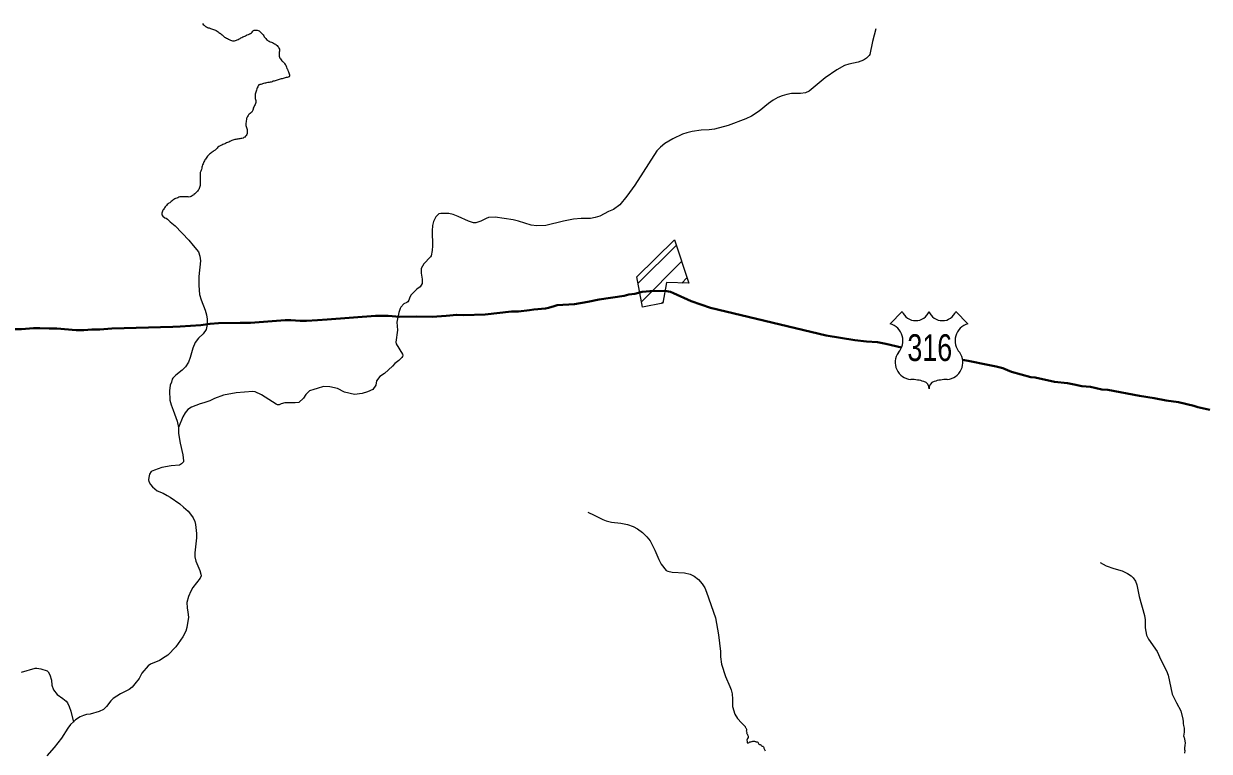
# Model space of a CAD drawing. Extents: x 553962 to 842807, y 8883888 to 9032388.
# Drawn here: x 610929 to 614032, y 8911161 to 8913066 of the extents above; entities that cross this region are included whole.
import ezdxf
from ezdxf.enums import TextEntityAlignment as Align

# ---------------------------------------------------------------- set-up
doc = ezdxf.new("R2010")
doc.units = 0
doc.header["$LTSCALE"] = 200
doc.layers.add('6', color=7, linetype='Continuous', lineweight=13)

msp = doc.modelspace()

# ---------------------------------------------------------------- linework, layer by layer
at = {"layer": '6'}
for p, q in [((612536.6, 8912385.5), (612637.1, 8912486)), ((612545.6, 8912337.9), (612650.9, 8912443.2)), ((612651.1, 8912386.8), (612664.7, 8912400.5)), ((612598.1, 8912333.9), (612602.5, 8912338.2))]:
    msp.add_line(p, q, dxfattribs=at)
at = {"layer": '6', "lineweight": 25}
for p, q in [((613196.5, 8912280.5), (613228.5, 8912312.5)), ((613368.3, 8912312.5), (613400.3, 8912280.5))]:
    msp.add_line(p, q, dxfattribs=at)
at = {"layer": '6'}
for points in [[(611397, 8913066), (611398.5, 8913063.9), (611400.7, 8913062.2), (611402.5, 8913060.4), (611404.7, 8913058.6), (611406.9, 8913057.2), (611409.4, 8913056.1), (611411.9, 8913055.3), (611414.3, 8913054.5), (611417.4, 8913053.4), (611420, 8913052.7), (611422.7, 8913051.8), (611425.5, 8913050.9), (611428.1, 8913050.1), (611430.4, 8913049), (611432.6, 8913047.7), (611434.7, 8913046.2), (611437.3, 8913044.6), (611439.4, 8913043), (611441.7, 8913041.3), (611443.8, 8913039.7), (611445.7, 8913038.1), (611448, 8913036.2), (611449.9, 8913034.5), (611452.1, 8913032.6), (611454.1, 8913030.9), (611456.5, 8913029.3), (611459.3, 8913027.7), (611461.8, 8913026.6), (611464.3, 8913025.3), (611466.6, 8913024.2), (611469.6, 8913022.7), (611472.2, 8913021.6), (611475.1, 8913021), (611477.7, 8913020.6), (611480.2, 8913020.6), (611482.9, 8913021.6), (611485.4, 8913022.6), (611487.7, 8913023.6), (611490.2, 8913024.5), (611492.8, 8913025.7), (611495.1, 8913027), (611497.1, 8913028.5), (611499.5, 8913029.9), (611502, 8913031.3), (611504.6, 8913032), (611507.2, 8913032.7), (611509.2, 8913034.3), (611511.5, 8913035.9), (611514, 8913036.9), (611516.8, 8913037.4), (611519.3, 8913038.6), (611520, 8913038.8), (611522.3, 8913040.1), (611524.5, 8913041.8), (611526.4, 8913043.5), (611528.1, 8913045.8), (611529.9, 8913047.7), (611532.3, 8913049), (611534.8, 8913049.2)], [(613159.1, 8913052.5), (613150.7, 8913018.9), (613143.3, 8912984.7), (613141.8, 8912982.2), (613135, 8912975.7), (613126.6, 8912970.5), (613113.2, 8912965.1), (613088.7, 8912959.4), (613077.6, 8912955.9), (613056.8, 8912945.1), (613026.4, 8912924.2), (612984.3, 8912889.5), (612975.3, 8912885), (612962, 8912882.7), (612949.3, 8912883.3), (612938.2, 8912882.9), (612926.3, 8912880.4), (612913.6, 8912876.7), (612902.5, 8912872.2), (612890.6, 8912865.5), (612878, 8912856.9), (612853.6, 8912836.8), (612833.4, 8912823.5), (612819.3, 8912816.9), (612772.4, 8912799.4), (612736.7, 8912790.1), (612723.2, 8912787.6), (612701.8, 8912787.2), (612678, 8912783.9), (612664.5, 8912780.4), (612652.7, 8912776.3), (612628.1, 8912764), (612606.6, 8912751.9), (612595.2, 8912743), (612585.7, 8912732.6), (612528.2, 8912642.8), (612507.4, 8912614.5), (612488.7, 8912591.9), (612472.2, 8912579.6), (612459.6, 8912574.3), (612436.4, 8912561.7), (612424.6, 8912558.2), (612412.7, 8912555.7), (612388.1, 8912556.3), (612367.4, 8912554.2), (612341.2, 8912549.2), (612295.2, 8912537.7), (612271.4, 8912536.9), (612257.2, 8912538.1), (612223.7, 8912549.1), (612210.3, 8912552.6), (612162.7, 8912559.7), (612144.9, 8912558.7), (612138.8, 8912556.3), (612125.4, 8912548.8), (612112.3, 8912544.7), (612106, 8912544.6), (612092.8, 8912549.1), (612065.9, 8912561.3), (612052.4, 8912566.6), (612041.2, 8912568.8), (612020.6, 8912568.7), (612015.4, 8912567.7), (612007.7, 8912559.9), (612001.2, 8912548)], [(611534.8, 8913049.2), (611537.3, 8913048.8), (611540, 8913048.5), (611542.5, 8913048.3), (611544.8, 8913047.1), (611546.9, 8913045.1), (611548.7, 8913043.4), (611551.1, 8913041.3), (611552.8, 8913039.4), (611555.1, 8913036.4), (611556.8, 8913034.2), (611558.5, 8913031.5), (611560.3, 8913029.1), (611562.5, 8913026.8), (611564.6, 8913024.6), (611566.6, 8913022.8), (611568.8, 8913021.3), (611571.4, 8913019.7), (611574.1, 8913018.7), (611577, 8913017.7), (611579.6, 8913016.7), (611582.4, 8913015.1)], [(611582.4, 8913015.1), (611585.3, 8913013.1), (611587.7, 8913011.9), (611589.8, 8913010.3), (611591.8, 8913008.4), (611593.6, 8913006.2), (611595.2, 8913004.2), (611596.8, 8913001.8), (611598.2, 8912998.9), (611598.5, 8912996.2), (611598, 8912993.7), (611597.6, 8912991.2), (611597.5, 8912988.7), (611597.5, 8912985.6), (611597.4, 8912982.9), (611597.5, 8912980.4), (611598, 8912977.9), (611599.4, 8912975.5), (611600.7, 8912973.4), (611602.5, 8912971), (611604.1, 8912968.9), (611606.2, 8912967.2), (611608.2, 8912965.7), (611610, 8912963.7), (611611.6, 8912961.6), (611613.1, 8912959.3), (611614.4, 8912957.1), (611615.5, 8912954.4), (611616.7, 8912951.6), (611617.8, 8912948.7), (611618.8, 8912946.4), (611620, 8912943.5), (611621.5, 8912939.9), (611622.6, 8912937.4), (611623.5, 8912934.9), (611624.2, 8912932.3), (611624.4, 8912929.4), (611623.5, 8912927), (611621.1, 8912925.6), (611618.3, 8912925.2), (611615.7, 8912924.9), (611613.1, 8912924.1), (611610.4, 8912923.3), (611607.7, 8912922.4), (611604.8, 8912921.8), (611602.4, 8912921.2), (611599.8, 8912920.6), (611597.3, 8912920), (611594.7, 8912919), (611592.2, 8912917.8), (611589.6, 8912917), (611586.9, 8912916.3), (611583.9, 8912915.7), (611581.2, 8912915), (611578.8, 8912914), (611576.2, 8912913), (611573.7, 8912912.3), (611570.8, 8912911.9), (611567.5, 8912911.6), (611564.6, 8912910.8), (611561.9, 8912910.3), (611559.5, 8912909.7), (611556.7, 8912908.9), (611554.1, 8912908.1), (611551.6, 8912907.6)], [(611551.6, 8912907.6), (611549.1, 8912906.8), (611546.5, 8912906.4), (611544.1, 8912905.3), (611542.3, 8912903.2), (611541.3, 8912900.8), (611540.1, 8912897.8), (611539.2, 8912895.4), (611538.1, 8912892.1), (611537, 8912889.5), (611536.2, 8912886.6), (611535.8, 8912884), (611534.9, 8912881.6), (611534.4, 8912879.1), (611534.4, 8912875.9), (611534.5, 8912873.1), (611534.8, 8912870.2), (611535.5, 8912867.5), (611535.9, 8912864.7), (611536.2, 8912862.1), (611536.2, 8912859.5), (611535.4, 8912856.9), (611534.4, 8912854.6), (611533.1, 8912851.8), (611531.8, 8912849.5), (611530.6, 8912846.9), (611529.7, 8912844.3), (611529.1, 8912841.9), (611528.2, 8912839), (611526.9, 8912836.3), (611525.5, 8912834.1), (611523.2, 8912832.4), (611521.2, 8912830.7), (611519.2, 8912829.2), (611517.3, 8912827.2), (611515.8, 8912825.1), (611514.4, 8912823)], [(611514.4, 8912823), (611513.2, 8912820.6), (611512.1, 8912818.1), (611511.7, 8912814.8), (611511.3, 8912811.7), (611510.9, 8912808.6), (611510.4, 8912805.7), (611510.3, 8912802.6), (611510.2, 8912799.7), (611510.8, 8912797.1), (611511.6, 8912794.2), (611512.6, 8912791.5), (611513.5, 8912789), (611513.7, 8912786.4), (611513.7, 8912783.8), (611513.6, 8912780.8), (611513.3, 8912778.2), (611512.4, 8912775.8), (611511, 8912773.3), (611509.5, 8912771.1), (611507.4, 8912769.1), (611505.2, 8912767.7), (611502.7, 8912766.2), (611499.8, 8912765.3), (611497, 8912764.9), (611494.4, 8912764.6), (611491.8, 8912764.3), (611489.3, 8912763.8), (611486.7, 8912763.4), (611484.2, 8912763), (611481.5, 8912762.6), (611478.4, 8912761.8), (611475.9, 8912760.8), (611473.2, 8912759.7), (611470.2, 8912758.4), (611467.9, 8912757.2), (611465.2, 8912756), (611462.3, 8912755), (611459.4, 8912753.8), (611457.2, 8912752.4), (611454.9, 8912751), (611452.6, 8912750.1), (611449.9, 8912749.3), (611446.9, 8912748.2), (611444.4, 8912747), (611441.5, 8912745.6), (611439.2, 8912744.3), (611436.5, 8912742.4), (611434.8, 8912740.4), (611433.3, 8912738.3), (611431.3, 8912736.6), (611429.4, 8912734.9), (611426.6, 8912732.7), (611424.2, 8912731.1), (611421.6, 8912729.2), (611419.5, 8912727.6), (611417.4, 8912726.1), (611415.1, 8912724.3), (611413.2, 8912722.5), (611411.4, 8912720.7), (611409.7, 8912718.6), (611407.8, 8912716.1), (611406, 8912713.8), (611404.5, 8912711.6), (611403.1, 8912709)], [(611403.1, 8912709), (611401.6, 8912706.8), (611400.3, 8912704.3), (611399.2, 8912701.8), (611398, 8912698.8), (611396.9, 8912696.2), (611395.6, 8912693.2), (611394.7, 8912690.2), (611394.6, 8912687.5), (611394.3, 8912684.4), (611393.4, 8912682), (611392.1, 8912679.5), (611390.9, 8912676.1), (611390.4, 8912673.4), (611390.4, 8912670.8), (611390.6, 8912668.1), (611390.9, 8912665.3), (611390.9, 8912662), (611390.8, 8912659.3), (611390.8, 8912656.5), (611390.8, 8912653.8), (611390.7, 8912651.2), (611390.7, 8912648.4), (611390.7, 8912645.5), (611390.6, 8912642.6), (611390.1, 8912639.8), (611389.2, 8912637.2), (611387.9, 8912634.5), (611386.7, 8912632.2), (611385.1, 8912629.7), (611383.5, 8912627.6), (611382, 8912625.6), (611380.2, 8912623.8), (611378.3, 8912621.9), (611376.3, 8912620.2), (611374.2, 8912618.5), (611373.7, 8912618.1)], [(611373.7, 8912618.1), (611371.9, 8912616.7), (611369.6, 8912615.1), (611367.3, 8912613.8), (611364.8, 8912612.9), (611362.1, 8912612.1), (611359.3, 8912612.2), (611356.5, 8912612.2), (611353.9, 8912612.2), (611351.2, 8912612.3), (611348.3, 8912612.3), (611345.3, 8912612.3), (611342.6, 8912612.4), (611340.1, 8912612.4), (611337.2, 8912612.4), (611334.3, 8912611.5), (611331.7, 8912610.2), (611329.2, 8912609.5), (611326.3, 8912608.5), (611324.2, 8912607.2), (611321.6, 8912605.7), (611319.4, 8912603.9), (611317.2, 8912602.1), (611315, 8912600.3), (611312.9, 8912598.8), (611310.8, 8912597.2), (611308.7, 8912595.7), (611306.6, 8912593.9), (611304.6, 8912592.3), (611302.8, 8912590.3), (611301, 8912588.3), (611299.3, 8912586.4), (611297.5, 8912584.1), (611296.1, 8912581.7), (611294.7, 8912579.5), (611293.2, 8912577.3), (611291.7, 8912574.7), (611290.9, 8912572.3), (611290.4, 8912569.7), (611290.2, 8912566.5), (611290.2, 8912565.6)], [(611290.2, 8912565.6), (611292.4, 8912562.4), (611298.3, 8912557.6), (611301.3, 8912556.6), (611305.3, 8912553.9), (611312.1, 8912547.1), (611324.9, 8912537), (611361.2, 8912499.1), (611371.9, 8912485.1), (611386, 8912468.5), (611390, 8912456.9), (611391.3, 8912445), (611386.8, 8912404.3), (611387.2, 8912380.4), (611389.2, 8912356.6), (611393.3, 8912343), (611403.5, 8912315.9), (611406.7, 8912303.9), (611408.7, 8912292), (611408.7, 8912278.4), (611406.1, 8912265.7), (611398.6, 8912253.7), (611386.1, 8912242.6), (611377.6, 8912231.2), (611371.5, 8912216.5), (611364.5, 8912191.8), (611360.2, 8912179.9), (611351.8, 8912167.9), (611343.1, 8912158.7), (611326.5, 8912145.7), (611318.7, 8912137.6), (611317.3, 8912135), (611315.6, 8912127.5), (611312.1, 8912119.3), (611310.2, 8912105)], [(612001.2, 8912548), (611998.8, 8912537.7), (611997.8, 8912523.3), (611998.9, 8912484.2), (611997.9, 8912472.3), (611995, 8912458.1), (611993.6, 8912455.4), (611976.2, 8912436.9), (611969.4, 8912425.1), (611969, 8912412.8), (611971.8, 8912397.5), (611972.1, 8912388.9), (611971.3, 8912385.8), (611966.1, 8912376.9), (611957.4, 8912370.8), (611942.7, 8912356), (611939.6, 8912350.1), (611936.9, 8912341.8), (611934.1, 8912337.6), (611931.6, 8912335.8), (611923.8, 8912332.9), (611915.6, 8912324.2), (611913.7, 8912320.5), (611910.8, 8912309.8), (611905.7, 8912284.3), (611906.7, 8912263.3), (611902.5, 8912231.9), (611903.9, 8912227.7), (611920, 8912201.1), (611920.7, 8912198.1), (611920.3, 8912194.8), (611918.3, 8912191.9), (611910.3, 8912183.8), (611900.1, 8912176.6), (611894.1, 8912169.3), (611873.3, 8912150.5), (611860.8, 8912142.2)], [(611860.8, 8912142.2), (611860.8, 8912142.2), (611852.4, 8912130.6), (611850.2, 8912119.3), (611842.5, 8912108), (611828.6, 8912102), (611814.7, 8912097.6), (611794.8, 8912095), (611768, 8912101.1), (611749.8, 8912110.6), (611730.3, 8912115), (611713.8, 8912115.8), (611696.5, 8912110.6), (611687.8, 8912108), (611677, 8912104.6), (611667, 8912095.5), (611661, 8912085.9), (611648.4, 8912074.2), (611639.3, 8912073.4), (611623.7, 8912073.4), (611612, 8912073.8), (611602.6, 8912070.7), (611597.1, 8912068.2), (611592.8, 8912068.2), (611589.7, 8912069.6), (611580.1, 8912076.4), (611551.1, 8912094.4), (611534.3, 8912102.2), (611528.4, 8912103.2), (611485, 8912099.4), (611451.7, 8912093.5), (611428, 8912084.7), (611415.6, 8912079), (611399.9, 8912073.1), (611390.8, 8912070.6), (611367.9, 8912061.9), (611358.4, 8912055.9), (611351.5, 8912047.5), (611345.1, 8912036.7), (611334, 8912009.2), (611334.2, 8911992.8), (611338.5, 8911967.8), (611345.2, 8911937.5), (611347.3, 8911921.7), (611346.6, 8911918.6), (611341.8, 8911913.5), (611336.8, 8911909.9), (611314.8, 8911908.6), (611290.6, 8911903.9), (611270.9, 8911897.5), (611262.2, 8911893.5), (611258, 8911886.6), (611255.8, 8911878.4), (611255.1, 8911871.9), (611256.3, 8911867.8), (611260.7, 8911859.5), (611265.5, 8911853.4), (611278.1, 8911843.3), (611294, 8911837.2), (611304.4, 8911830.6), (611312.3, 8911826.8), (611337.4, 8911809.1), (611346.5, 8911800.1), (611358.8, 8911790), (611365.5, 8911782.4)], [(611310.2, 8912105), (611311.4, 8912080.3), (611314.6, 8912068.4), (611320.3, 8912054.6), (611330, 8912025.5), (611334, 8912009.2)], [(611365.5, 8911782.4), (611372.5, 8911772.3), (611376.6, 8911762.8), (611378.7, 8911755.3), (611381.2, 8911731.8), (611381, 8911720.4), (611376.7, 8911680.5), (611376.8, 8911670.6), (611379.1, 8911658.8), (611389.3, 8911634.7), (611392.4, 8911624.7), (611392.8, 8911620.8), (611390.2, 8911614.4), (611371.5, 8911590.3), (611366.1, 8911580.4), (611360.3, 8911566.7), (611355.8, 8911550.8), (611356.1, 8911536.6), (611358.7, 8911525.1), (611359.8, 8911512.8), (611355.3, 8911485.4), (611352.6, 8911476.1), (611345.4, 8911461.1), (611327.1, 8911434.5), (611305.5, 8911413.2), (611299.2, 8911408.2), (611283.9, 8911399.1), (611260.6, 8911389.7), (611254.3, 8911385.1), (611238.1, 8911365.5), (611230.6, 8911352.3), (611219.7, 8911337.7), (611212.4, 8911329.5), (611204.8, 8911322.9), (611181.7, 8911312.1), (611162.9, 8911299.7), (611156.4, 8911293.6)], [(612405.4, 8911786.9), (612421.9, 8911779.7), (612444.2, 8911767.9), (612452.9, 8911764.7), (612467, 8911761.3), (612491.4, 8911758.4), (612508.9, 8911754.9), (612524, 8911749.8), (612535, 8911743.9), (612548.6, 8911733.8), (612559.7, 8911722.7), (612568.1, 8911711.9), (612580.6, 8911688.2), (612590.9, 8911663.6), (612597.2, 8911651.2), (612610.8, 8911634.7), (612615.1, 8911632.4), (612626.2, 8911629.9), (612658.6, 8911628.8), (612673.5, 8911625.1), (612683.9, 8911620.1), (612694.8, 8911611.3), (612705, 8911599.6), (612711.5, 8911589.3), (612716.3, 8911577.6), (612739.5, 8911510.5), (612747.7, 8911466.3), (612752.2, 8911422.9), (612752.6, 8911408.8), (612755.4, 8911389), (612765.9, 8911357.3), (612777.4, 8911331.4), (612780.4, 8911322.6), (612782.9, 8911311.6), (612784.4, 8911297.5), (612784.2, 8911278.4), (612790.5, 8911258.6), (612797.4, 8911247.3), (612807.2, 8911235.8), (612817.1, 8911225.9)], [(613746.6, 8911655.6), (613761.8, 8911647), (613782.4, 8911639.6), (613803.8, 8911633.7), (613818.3, 8911626.8), (613827.9, 8911620.8), (613832.9, 8911615.2), (613838.7, 8911606.9), (613842.3, 8911596.7), (613848.4, 8911566.1), (613862.4, 8911516.5), (613864.1, 8911505.6), (613864.4, 8911484.4), (613867.7, 8911465.5), (613872.8, 8911454.6), (613895.5, 8911422.3), (613905.6, 8911400.5), (613920.2, 8911371.9), (613924.2, 8911361), (613935.1, 8911310.7), (613946.5, 8911288.1), (613957.4, 8911267.5), (613963, 8911245.3)], [(610922.6, 8911368.1), (610958.8, 8911378.9), (610962.8, 8911379.3), (610973.9, 8911377.4), (610989.7, 8911371.9), (610992.6, 8911369.1), (610997.3, 8911361.4), (611001, 8911347.8), (611001.9, 8911334.6), (611006.5, 8911322), (611016.2, 8911310.1), (611031.4, 8911299.8), (611040.2, 8911292.3), (611043.1, 8911288), (611047.8, 8911278.4), (611052.3, 8911266.4), (611058.9, 8911237.5)], [(611156.4, 8911293.6), (611145.6, 8911278.9), (611145.6, 8911278.9), (611137.9, 8911270.6), (611126.4, 8911265.2), (611103, 8911258.7), (611093.1, 8911257.4), (611085.3, 8911255.4), (611076.2, 8911251.3), (611063.8, 8911244.1), (611059.2, 8911238.6), (611051.4, 8911231.2), (611044.1, 8911221.8), (611027.5, 8911195.8), (611008, 8911171.5), (610989.4, 8911149.8)], [(612817.1, 8911225.9), (612817.4, 8911225), (612818, 8911223.9), (612818.6, 8911222.4), (612819.6, 8911220.8), (612820.4, 8911219.5), (612820.6, 8911218.7), (612820.6, 8911217.4), (612820.3, 8911215.9), (612820.2, 8911213.9), (612820.4, 8911213), (612821.1, 8911211.6), (612821.3, 8911210.5), (612821, 8911209.4)], [(613963, 8911245.3), (613963.4, 8911239.5), (613963.5, 8911237), (613964, 8911233.7), (613964.6, 8911229.1), (613965.9, 8911221.6), (613966.2, 8911220), (613966.3, 8911218.8), (613966.4, 8911218.5)], [(612821, 8911209.4), (612821.6, 8911208.3), (612822.4, 8911206.7), (612823.2, 8911204.4), (612824.9, 8911200.9), (612825.3, 8911199.8), (612825.2, 8911198.6), (612824.6, 8911197.1), (612823.1, 8911195.1), (612822, 8911193.1), (612821.4, 8911190.8), (612822.3, 8911187), (612822.3, 8911184.5), (612822.3, 8911183.5)], [(613966, 8911218.5), (613966.2, 8911213.3), (613966.1, 8911210.4), (613965.8, 8911207), (613965.3, 8911205.2), (613964.9, 8911202.2), (613965.7, 8911199.6), (613966.6, 8911197.7), (613967.8, 8911188.8), (613968.6, 8911182.6), (613968.1, 8911177), (613967.4, 8911169.7), (613967.3, 8911166.2), (613967.7, 8911163.2), (613967.1, 8911156.4)], [(612822.3, 8911183.6), (612823.9, 8911183.1), (612824.8, 8911183), (612825.5, 8911183.1), (612826.4, 8911183.6), (612827.5, 8911185), (612828.1, 8911185.7), (612829, 8911186), (612830.5, 8911186), (612832.3, 8911185.9), (612834.3, 8911186.6), (612835.2, 8911187), (612837.1, 8911188), (612838.2, 8911188.2), (612839.3, 8911188), (612841.9, 8911187.6), (612843.1, 8911187.2), (612844.3, 8911186.8), (612845.2, 8911186.6)], [(612845.8, 8911186.4), (612847.8, 8911186.2), (612848.8, 8911185.9), (612850.1, 8911185.3), (612851.1, 8911183.4), (612851.8, 8911182.1), (612853.2, 8911180.4), (612854.8, 8911179.4), (612856.6, 8911178.8), (612858, 8911178), (612859.3, 8911176.8), (612860.2, 8911175.8), (612861.6, 8911175.2), (612863.6, 8911174.4), (612864.9, 8911173.1), (612865.7, 8911171.2), (612866, 8911169.8), (612866.6, 8911168.1), (612868, 8911166.1), (612868.8, 8911164.7), (612869.4, 8911162.7), (612869.5, 8911162.2)]]:
    msp.add_lwpolyline(points, dxfattribs=at)
msp.add_lwpolyline([(612533.2, 8912403.4), (612632.5, 8912500.1), (612669.3, 8912386.3), (612611.2, 8912388.1), (612601.8, 8912334.6), (612548.3, 8912323.5)], close=True, dxfattribs=at)
at = {"layer": '6', "lineweight": 40}
for points in [[(611849.1, 8912301.5), (611883.1, 8912301.1), (611912.9, 8912298.6), (611956.6, 8912299.4), (611998, 8912298.2), (612034.4, 8912300.8), (612062.1, 8912304), (612080.2, 8912303.3), (612136.2, 8912305), (612205.9, 8912312.1), (612224, 8912312.5), (612252.3, 8912315.6), (612263.9, 8912317.7), (612294.8, 8912320.4), (612302.5, 8912322), (612316.8, 8912326.8), (612325.2, 8912328.8), (612370.8, 8912332), (612405.4, 8912337.7), (612435.2, 8912344), (612500.6, 8912353.4), (612512.3, 8912356.6), (612528.3, 8912358.5), (612547.5, 8912363.6), (612568.3, 8912366), (612607.2, 8912366.8), (612622, 8912364.3), (612629.4, 8912360.3), (612675.8, 8912339.5), (612726, 8912322.1), (613028.9, 8912249.9)], [(611319, 8912272.7), (611337.8, 8912273.2), (611392.4, 8912276.9), (611416.3, 8912280.4), (611438.8, 8912282.1), (611495.6, 8912282.8)], [(611495.6, 8912282.8), (611522.6, 8912283.1), (611612.8, 8912289.8), (611627.7, 8912289.9), (611652.6, 8912288.3), (611668.8, 8912288.2), (611697.4, 8912289.8), (611723, 8912291.6), (611849.1, 8912301.5)], [(610786.1, 8912264.2), (610808.2, 8912264.2), (610849.7, 8912265.4), (610879.2, 8912265), (610901.3, 8912266.3), (610922.7, 8912266), (610954.4, 8912268.5), (610970.6, 8912268.9), (610994.9, 8912267.6), (611015.5, 8912267.9), (611066.4, 8912263.8), (611086.2, 8912263.8), (611106.9, 8912265.3), (611127.5, 8912265.4), (611159.2, 8912268), (611319, 8912272.7)], [(613028.9, 8912249.9), (613104.3, 8912237.7), (613134.5, 8912234.3), (613163.2, 8912232.2), (613185.3, 8912228.2), (613226.8, 8912218.5)], [(613386.4, 8912186.2), (613401.2, 8912183.6), (613452.1, 8912172.7), (613474.2, 8912168.8), (613491.2, 8912163.9), (613503.7, 8912158.5), (613514.7, 8912154.8), (613564.8, 8912141), (613576.6, 8912139.3), (613626.7, 8912128.5), (613660.6, 8912124.5), (613678.3, 8912121.5), (613698.2, 8912117), (613721.1, 8912115.6), (613750.5, 8912108.4), (613766.3, 8912107.4), (613849.7, 8912091.9), (613888.1, 8912085.9), (613919, 8912079.5), (613951.5, 8912074.8), (613991.2, 8912065.2), (614002.3, 8912061.8), (614033.2, 8912054.9)]]:
    msp.add_lwpolyline(points, dxfattribs=at)
at = {"layer": '6', "lineweight": 25}
for centre, radius, start, end in [((613263.4, 8912325.9), 37.4, 200.9593, 339.0407), ((613333.4, 8912325.9), 37.4, 200.9593, 339.0407), ((613184.1, 8912236.1), 46.1, 317.5721, 74.3689), ((613412.7, 8912236.1), 46.1, 105.6277, 222.4279), ((613254.8, 8912179.1), 44.9, 144.7373, 264.6578), ((613342, 8912179.1), 44.9, 275.3422, 35.2627), ((613250.4, 8912016.4), 118, 72.8937, 89.9006), ((613279.5, 8912111.1), 18.9, 357.6934, 72.9296), ((613317.3, 8912111.1), 18.9, 107.0704, 182.3065), ((613346.4, 8912016.4), 118, 90.0994, 107.1063)]:
    msp.add_arc(centre, radius, start, end, dxfattribs=at)

# ---------------------------------------------------------------- texts
at = {"layer": '6', "width": 0.75}
msp.add_text('316', height=70, dxfattribs=at).set_placement((613300.4, 8912182.9), align=Align.CENTER)

doc.saveas('drawing.dxf')
